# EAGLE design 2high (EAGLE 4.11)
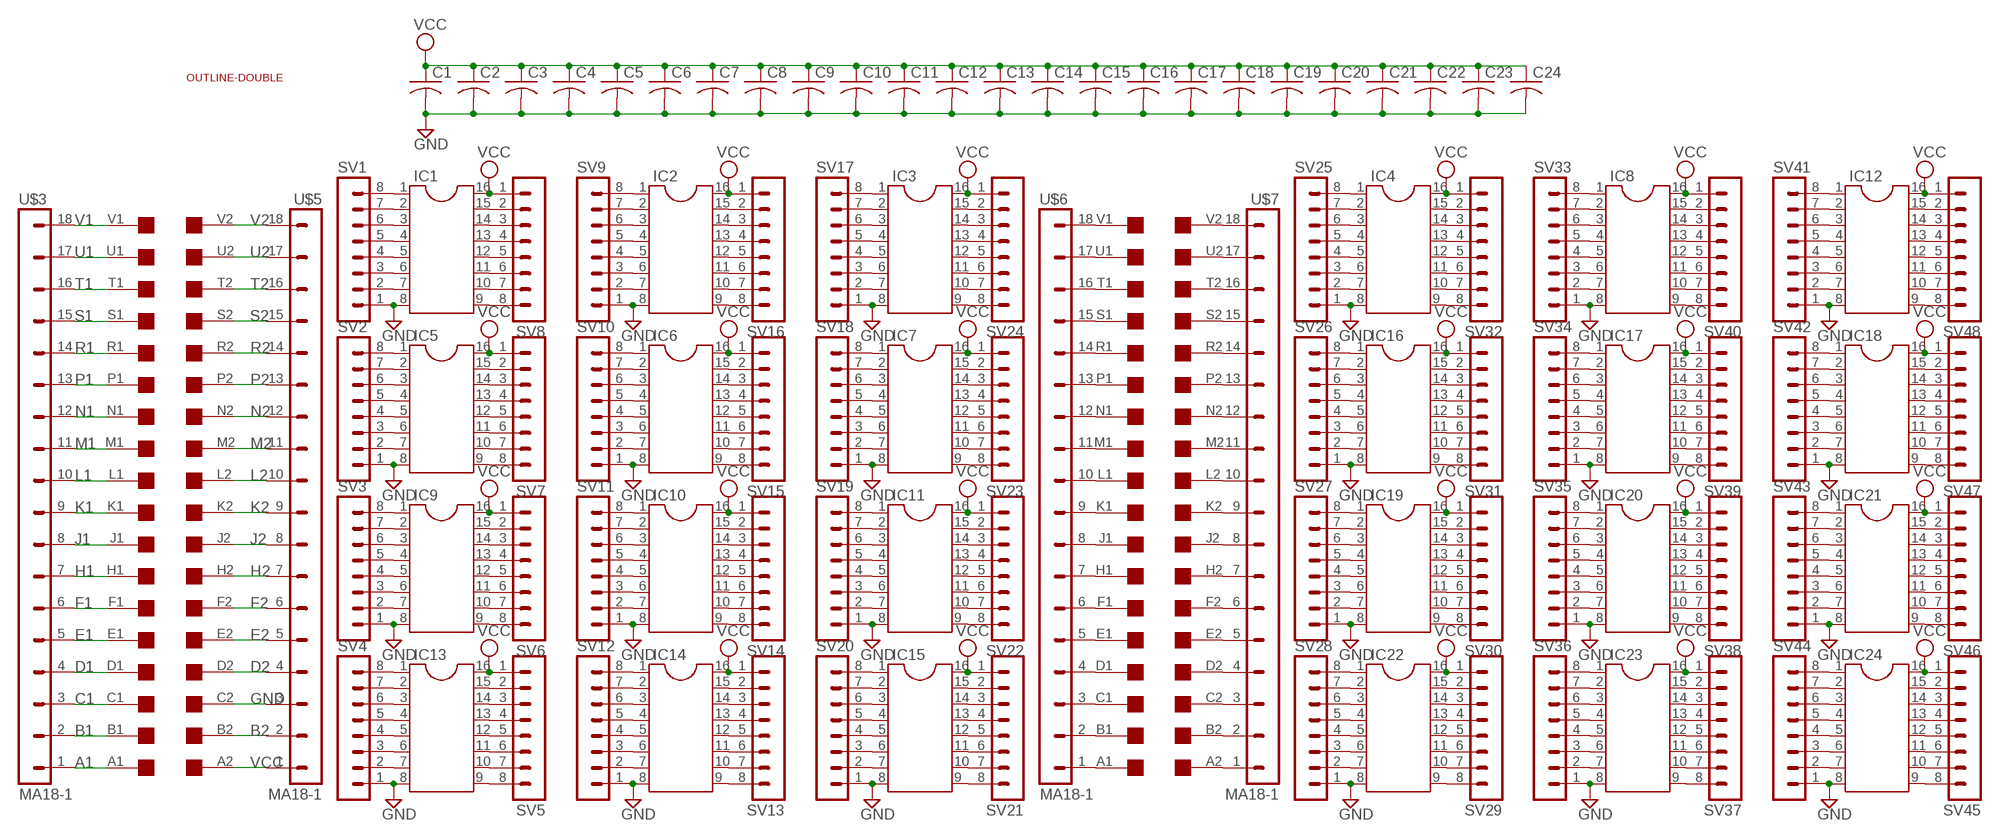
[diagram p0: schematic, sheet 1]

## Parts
C1  C-US050-025X075  [C050-025X075]
C2  C-US050-025X075  [C050-025X075]
C3  C-US050-025X075  [C050-025X075]
C4  C-US050-025X075  [C050-025X075]
C5  C-US050-025X075  [C050-025X075]
C6  C-US050-025X075  [C050-025X075]
C7  C-US050-025X075  [C050-025X075]
C8  C-US050-025X075  [C050-025X075]
C9  C-US050-025X075  [C050-025X075]
C10  C-US050-025X075  [C050-025X075]
C11  C-US050-025X075  [C050-025X075]
C12  C-US050-025X075  [C050-025X075]
C13  C-US050-025X075  [C050-025X075]
C14  C-US050-025X075  [C050-025X075]
C15  C-US050-025X075  [C050-025X075]
C16  C-US050-025X075  [C050-025X075]
C17  C-US050-025X075  [C050-025X075]
C18  C-US050-025X075  [C050-025X075]
C19  C-US050-025X075  [C050-025X075]
C20  C-US050-025X075  [C050-025X075]
C21  C-US050-025X075  [C050-025X075]
C22  C-US050-025X075  [C050-025X075]
C23  C-US050-025X075  [C050-025X075]
C24  C-US050-025X075  [C050-025X075]
IC1  DIL16  [DIL16]
IC2  DIL16  [DIL16]
IC3  DIL16  [DIL16]
IC4  DIL16  [DIL16]
IC5  DIL16  [DIL16]
IC6  DIL16  [DIL16]
IC7  DIL16  [DIL16]
IC8  DIL16  [DIL16]
IC9  DIL16  [DIL16]
IC10  DIL16  [DIL16]
IC11  DIL16  [DIL16]
IC12  DIL16  [DIL16]
IC13  DIL16  [DIL16]
IC14  DIL16  [DIL16]
IC15  DIL16  [DIL16]
IC16  DIL16  [DIL16]
IC17  DIL16  [DIL16]
IC18  DIL16  [DIL16]
IC19  DIL16  [DIL16]
IC20  DIL16  [DIL16]
IC21  DIL16  [DIL16]
IC22  DIL16  [DIL16]
IC23  DIL16  [DIL16]
IC24  DIL16  [DIL16]
SV1  MA08-1  [MA08-1]
SV2  MA08-1  [MA08-1]
SV3  MA08-1  [MA08-1]
SV4  MA08-1  [MA08-1]
SV5  MA08-1  [MA08-1]
SV6  MA08-1  [MA08-1]
SV7  MA08-1  [MA08-1]
SV8  MA08-1  [MA08-1]
SV9  MA08-1  [MA08-1]
SV10  MA08-1  [MA08-1]
SV11  MA08-1  [MA08-1]
SV12  MA08-1  [MA08-1]
SV13  MA08-1  [MA08-1]
SV14  MA08-1  [MA08-1]
SV15  MA08-1  [MA08-1]
SV16  MA08-1  [MA08-1]
SV17  MA08-1  [MA08-1]
SV18  MA08-1  [MA08-1]
SV19  MA08-1  [MA08-1]
SV20  MA08-1  [MA08-1]
SV21  MA08-1  [MA08-1]
SV22  MA08-1  [MA08-1]
SV23  MA08-1  [MA08-1]
SV24  MA08-1  [MA08-1]
SV25  MA08-1  [MA08-1]
SV26  MA08-1  [MA08-1]
SV27  MA08-1  [MA08-1]
SV28  MA08-1  [MA08-1]
SV29  MA08-1  [MA08-1]
SV30  MA08-1  [MA08-1]
SV31  MA08-1  [MA08-1]
SV32  MA08-1  [MA08-1]
SV33  MA08-1  [MA08-1]
SV34  MA08-1  [MA08-1]
SV35  MA08-1  [MA08-1]
SV36  MA08-1  [MA08-1]
SV37  MA08-1  [MA08-1]
SV38  MA08-1  [MA08-1]
SV39  MA08-1  [MA08-1]
SV40  MA08-1  [MA08-1]
SV41  MA08-1  [MA08-1]
SV42  MA08-1  [MA08-1]
SV43  MA08-1  [MA08-1]
SV44  MA08-1  [MA08-1]
SV45  MA08-1  [MA08-1]
SV46  MA08-1  [MA08-1]
SV47  MA08-1  [MA08-1]
SV48  MA08-1  [MA08-1]
U$1  OUTLINE-DOUBLE  [DOUBLE]
U$2  EDGE-2CONNECTOR  [EDGE-CON2]
U$3  MA18-1  [MA18-1]
U$4  EDGE-2CONNECTOR  [EDGE-CON2]
U$5  MA18-1  [MA18-1]
U$6  MA18-1  [MA18-1]
U$7  MA18-1  [MA18-1]

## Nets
A1: U$3.1 U$4.A1
B1: U$3.2 U$4.B1
B2: U$4.B2 U$5.2
C1: U$3.3 U$4.C1
D1: U$3.4 U$4.D1
D2: U$4.D2 U$5.4
E1: U$3.5 U$4.E1
E2: U$4.E2 U$5.5
F1: U$3.6 U$4.F1
F2: U$4.F2 U$5.6
GND: C1.2 C2.2 C3.2 C4.2 C5.2 C6.2 C7.2 C8.2 C9.2 C10.2 C11.2 C12.2 C13.2 C14.2 C15.2 C16.2 C17.2 C18.2 C19.2 C20.2 C21.2 C22.2 C23.2 C24.2 IC1.8 IC2.8 IC3.8 IC4.8 IC5.8 IC6.8 IC7.8 IC8.8 IC9.8 IC10.8 IC11.8 IC12.8 IC13.8 IC14.8 IC15.8 IC16.8 IC17.8 IC18.8 IC19.8 IC20.8 IC21.8 IC22.8 IC23.8 IC24.8 SV1.1 SV2.1 SV3.1 SV4.1 SV9.1 SV10.1 SV11.1 SV12.1 SV17.1 SV18.1 SV19.1 SV20.1 SV25.1 SV26.1 SV27.1 SV28.1 SV33.1 SV34.1 SV35.1 SV36.1 SV41.1 SV42.1 SV43.1 SV44.1 U$4.C2 U$5.3
H1: U$3.7 U$4.H1
H2: U$4.H2 U$5.7
J1: U$3.8 U$4.J1
J2: U$4.J2 U$5.8
K1: U$3.9 U$4.K1
K2: U$4.K2 U$5.9
L1: U$3.10 U$4.L1
L2: U$4.L2 U$5.10
M1: U$3.11 U$4.M1
M2: U$4.M2 U$5.11
N1: U$3.12 U$4.N1
N2: U$4.N2 U$5.12
N$1: IC1.7 SV1.2
N$2: IC1.6 SV1.3
N$3: IC1.5 SV1.4
N$4: IC1.4 SV1.5
N$5: IC1.3 SV1.6
N$6: IC1.2 SV1.7
N$7: IC1.1 SV1.8
N$8: IC5.7 SV2.2
N$9: IC5.6 SV2.3
N$10: IC5.5 SV2.4
N$11: IC5.4 SV2.5
N$12: IC5.3 SV2.6
N$13: IC5.2 SV2.7
N$14: IC5.1 SV2.8
N$15: IC9.7 SV3.2
N$16: IC9.6 SV3.3
N$17: IC9.5 SV3.4
N$18: IC9.4 SV3.5
N$19: IC9.3 SV3.6
N$20: IC9.2 SV3.7
N$21: IC9.1 SV3.8
N$22: IC13.7 SV4.2
N$23: IC13.6 SV4.3
N$24: IC13.5 SV4.4
N$25: IC13.4 SV4.5
N$26: IC13.3 SV4.6
N$27: IC13.2 SV4.7
N$28: IC13.1 SV4.8
N$29: IC2.1 SV9.8
N$30: IC2.2 SV9.7
N$31: IC2.3 SV9.6
N$32: IC2.4 SV9.5
N$33: IC2.5 SV9.4
N$34: IC2.6 SV9.3
N$35: IC2.7 SV9.2
N$36: IC6.1 SV10.8
N$37: IC6.2 SV10.7
N$38: IC6.3 SV10.6
N$39: IC6.4 SV10.5
N$40: IC6.5 SV10.4
N$41: IC6.6 SV10.3
N$42: IC6.7 SV10.2
N$43: IC10.1 SV11.8
N$44: IC10.2 SV11.7
N$45: IC10.3 SV11.6
N$46: IC10.4 SV11.5
N$47: IC10.5 SV11.4
N$48: IC10.6 SV11.3
N$49: IC10.7 SV11.2
N$50: IC14.1 SV12.8
N$51: IC14.2 SV12.7
N$52: IC14.3 SV12.6
N$53: IC14.4 SV12.5
N$54: IC14.5 SV12.4
N$55: IC14.6 SV12.3
N$56: IC14.7 SV12.2
N$57: IC6.15 SV15.2
N$58: IC6.14 SV15.3
N$59: IC6.13 SV15.4
N$60: IC6.12 SV15.5
N$61: IC6.11 SV15.6
N$62: IC6.10 SV15.7
N$63: IC6.9 SV15.8
N$64: IC10.15 SV14.2
N$65: IC10.14 SV14.3
N$66: IC10.13 SV14.4
N$67: IC10.12 SV14.5
N$68: IC10.11 SV14.6
N$69: IC10.10 SV14.7
N$70: IC10.9 SV14.8
N$71: IC1.9 SV8.8
N$72: IC1.10 SV8.7
N$73: IC1.11 SV8.6
N$74: IC1.12 SV8.5
N$75: IC1.13 SV8.4
N$76: IC1.14 SV8.3
N$77: IC1.15 SV8.2
N$78: IC5.9 SV7.8
N$79: IC5.10 SV7.7
N$80: IC5.11 SV7.6
N$81: IC5.12 SV7.5
N$82: IC5.13 SV7.4
N$83: IC5.14 SV7.3
N$84: IC5.15 SV7.2
N$85: IC2.15 SV16.2
N$86: IC2.14 SV16.3
N$87: IC2.13 SV16.4
N$88: IC2.12 SV16.5
N$89: IC2.11 SV16.6
N$90: IC2.10 SV16.7
N$91: IC2.9 SV16.8
N$92: IC13.15 SV5.2
N$93: IC13.14 SV5.3
N$94: IC13.13 SV5.4
N$95: IC13.12 SV5.5
N$96: IC13.11 SV5.6
N$97: IC13.10 SV5.7
N$98: IC13.9 SV5.8
N$99: IC9.15 SV6.2
N$100: IC9.14 SV6.3
N$101: IC9.13 SV6.4
N$102: IC9.12 SV6.5
N$103: IC9.11 SV6.6
N$104: IC9.10 SV6.7
N$105: IC9.9 SV6.8
N$106: IC14.15 SV13.2
N$107: IC14.14 SV13.3
N$108: IC14.13 SV13.4
N$109: IC14.12 SV13.5
N$110: IC14.11 SV13.6
N$111: IC14.10 SV13.7
N$112: IC14.9 SV13.8
N$113: IC3.7 SV17.2
N$114: IC3.6 SV17.3
N$115: IC3.5 SV17.4
N$116: IC3.4 SV17.5
N$117: IC3.3 SV17.6
N$118: IC3.2 SV17.7
N$119: IC3.1 SV17.8
N$120: IC7.7 SV18.2
N$121: IC7.6 SV18.3
N$122: IC7.5 SV18.4
N$123: IC7.4 SV18.5
N$124: IC7.3 SV18.6
N$125: IC7.2 SV18.7
N$126: IC7.1 SV18.8
N$127: IC11.7 SV19.2
N$128: IC11.6 SV19.3
N$129: IC11.5 SV19.4
N$130: IC11.4 SV19.5
N$131: IC11.3 SV19.6
N$132: IC11.2 SV19.7
N$133: IC11.1 SV19.8
N$134: IC15.7 SV20.2
N$135: IC15.6 SV20.3
N$136: IC15.5 SV20.4
N$137: IC15.4 SV20.5
N$138: IC15.3 SV20.6
N$139: IC15.2 SV20.7
N$140: IC15.1 SV20.8
N$141: IC15.15 SV21.2
N$142: IC15.14 SV21.3
N$143: IC15.13 SV21.4
N$144: IC15.12 SV21.5
N$145: IC15.11 SV21.6
N$146: IC15.10 SV21.7
N$147: IC15.9 SV21.8
N$148: IC11.15 SV22.2
N$149: IC11.14 SV22.3
N$150: IC11.13 SV22.4
N$151: IC11.12 SV22.5
N$152: IC11.11 SV22.6
N$153: IC11.10 SV22.7
N$154: IC11.9 SV22.8
N$155: IC7.15 SV23.2
N$156: IC7.14 SV23.3
N$157: IC7.13 SV23.4
N$158: IC7.12 SV23.5
N$159: IC7.11 SV23.6
N$160: IC7.10 SV23.7
N$161: IC7.9 SV23.8
N$162: IC3.15 SV24.2
N$163: IC3.14 SV24.3
N$164: IC3.13 SV24.4
N$165: IC3.12 SV24.5
N$166: IC3.11 SV24.6
N$167: IC3.10 SV24.7
N$168: IC3.9 SV24.8
N$169: U$2.A2 U$7.1
N$170: U$2.A1 U$6.1
N$171: U$2.B1 U$6.2
N$172: U$2.B2 U$7.2
N$173: U$2.C2 U$7.3
N$174: U$2.C1 U$6.3
N$175: U$2.D1 U$6.4
N$176: U$2.D2 U$7.4
N$177: U$2.E2 U$7.5
N$178: U$2.E1 U$6.5
N$179: U$2.F1 U$6.6
N$180: U$2.F2 U$7.6
N$181: U$2.H2 U$7.7
N$182: U$2.H1 U$6.7
N$183: U$2.J1 U$6.8
N$184: U$2.J2 U$7.8
N$185: U$2.K2 U$7.9
N$186: U$2.K1 U$6.9
N$187: U$2.L1 U$6.10
N$188: U$2.L2 U$7.10
N$189: U$2.M2 U$7.11
N$190: U$2.M1 U$6.11
N$191: U$2.N1 U$6.12
N$192: U$2.P1 U$6.13
N$193: U$2.P2 U$7.13
N$194: U$2.N2 U$7.12
N$195: U$2.V1 U$6.18
N$196: U$2.U1 U$6.17
N$197: U$2.T1 U$6.16
N$198: U$2.S1 U$6.15
N$199: U$2.R1 U$6.14
N$200: U$2.V2 U$7.18
N$201: U$2.U2 U$7.17
N$202: U$2.T2 U$7.16
N$203: U$2.S2 U$7.15
N$204: U$2.R2 U$7.14
N$205: IC4.7 SV25.2
N$206: IC4.6 SV25.3
N$207: IC4.5 SV25.4
N$208: IC4.4 SV25.5
N$209: IC4.3 SV25.6
N$210: IC4.2 SV25.7
N$211: IC4.1 SV25.8
N$212: IC16.7 SV26.2
N$213: IC16.6 SV26.3
N$214: IC16.5 SV26.4
N$215: IC16.4 SV26.5
N$216: IC16.3 SV26.6
N$217: IC16.2 SV26.7
N$218: IC16.1 SV26.8
N$219: IC19.7 SV27.2
N$220: IC19.6 SV27.3
N$221: IC19.5 SV27.4
N$222: IC19.4 SV27.5
N$223: IC19.3 SV27.6
N$224: IC19.2 SV27.7
N$225: IC19.1 SV27.8
N$226: IC22.7 SV28.2
N$227: IC22.6 SV28.3
N$228: IC22.5 SV28.4
N$229: IC22.4 SV28.5
N$230: IC22.3 SV28.6
N$231: IC22.2 SV28.7
N$232: IC22.1 SV28.8
N$233: IC8.1 SV33.8
N$234: IC8.2 SV33.7
N$235: IC8.3 SV33.6
N$236: IC8.4 SV33.5
N$237: IC8.5 SV33.4
N$238: IC8.6 SV33.3
N$239: IC8.7 SV33.2
N$240: IC17.1 SV34.8
N$241: IC17.2 SV34.7
N$242: IC17.3 SV34.6
N$243: IC17.4 SV34.5
N$244: IC17.5 SV34.4
N$245: IC17.6 SV34.3
N$246: IC17.7 SV34.2
N$247: IC20.1 SV35.8
N$248: IC20.2 SV35.7
N$249: IC20.3 SV35.6
N$250: IC20.4 SV35.5
N$251: IC20.5 SV35.4
N$252: IC20.6 SV35.3
N$253: IC20.7 SV35.2
N$254: IC23.1 SV36.8
N$255: IC23.2 SV36.7
N$256: IC23.3 SV36.6
N$257: IC23.4 SV36.5
N$258: IC23.5 SV36.4
N$259: IC23.6 SV36.3
N$260: IC23.7 SV36.2
N$261: IC17.15 SV39.2
N$262: IC17.14 SV39.3
N$263: IC17.13 SV39.4
N$264: IC17.12 SV39.5
N$265: IC17.11 SV39.6
N$266: IC17.10 SV39.7
N$267: IC17.9 SV39.8
N$268: IC20.15 SV38.2
N$269: IC20.14 SV38.3
N$270: IC20.13 SV38.4
N$271: IC20.12 SV38.5
N$272: IC20.11 SV38.6
N$273: IC20.10 SV38.7
N$274: IC20.9 SV38.8
N$275: IC4.9 SV32.8
N$276: IC4.10 SV32.7
N$277: IC4.11 SV32.6
N$278: IC4.12 SV32.5
N$279: IC4.13 SV32.4
N$280: IC4.14 SV32.3
N$281: IC4.15 SV32.2
N$282: IC16.9 SV31.8
N$283: IC16.10 SV31.7
N$284: IC16.11 SV31.6
N$285: IC16.12 SV31.5
N$286: IC16.13 SV31.4
N$287: IC16.14 SV31.3
N$288: IC16.15 SV31.2
N$289: IC8.15 SV40.2
N$290: IC8.14 SV40.3
N$291: IC8.13 SV40.4
N$292: IC8.12 SV40.5
N$293: IC8.11 SV40.6
N$294: IC8.10 SV40.7
N$295: IC8.9 SV40.8
N$296: IC22.15 SV29.2
N$297: IC22.14 SV29.3
N$298: IC22.13 SV29.4
N$299: IC22.12 SV29.5
N$300: IC22.11 SV29.6
N$301: IC22.10 SV29.7
N$302: IC22.9 SV29.8
N$303: IC19.15 SV30.2
N$304: IC19.14 SV30.3
N$305: IC19.13 SV30.4
N$306: IC19.12 SV30.5
N$307: IC19.11 SV30.6
N$308: IC19.10 SV30.7
N$309: IC19.9 SV30.8
N$310: IC23.15 SV37.2
N$311: IC23.14 SV37.3
N$312: IC23.13 SV37.4
N$313: IC23.12 SV37.5
N$314: IC23.11 SV37.6
N$315: IC23.10 SV37.7
N$316: IC23.9 SV37.8
N$317: IC12.7 SV41.2
N$318: IC12.6 SV41.3
N$319: IC12.5 SV41.4
N$320: IC12.4 SV41.5
N$321: IC12.3 SV41.6
N$322: IC12.2 SV41.7
N$323: IC12.1 SV41.8
N$324: IC18.7 SV42.2
N$325: IC18.6 SV42.3
N$326: IC18.5 SV42.4
N$327: IC18.4 SV42.5
N$328: IC18.3 SV42.6
N$329: IC18.2 SV42.7
N$330: IC18.1 SV42.8
N$331: IC21.7 SV43.2
N$332: IC21.6 SV43.3
N$333: IC21.5 SV43.4
N$334: IC21.4 SV43.5
N$335: IC21.3 SV43.6
N$336: IC21.2 SV43.7
N$337: IC21.1 SV43.8
N$338: IC24.7 SV44.2
N$339: IC24.6 SV44.3
N$340: IC24.5 SV44.4
N$341: IC24.4 SV44.5
N$342: IC24.3 SV44.6
N$343: IC24.2 SV44.7
N$344: IC24.1 SV44.8
N$345: IC24.15 SV45.2
N$346: IC24.14 SV45.3
N$347: IC24.13 SV45.4
N$348: IC24.12 SV45.5
N$349: IC24.11 SV45.6
N$350: IC24.10 SV45.7
N$351: IC24.9 SV45.8
N$352: IC21.15 SV46.2
N$353: IC21.14 SV46.3
N$354: IC21.13 SV46.4
N$355: IC21.12 SV46.5
N$356: IC21.11 SV46.6
N$357: IC21.10 SV46.7
N$358: IC21.9 SV46.8
N$359: IC18.15 SV47.2
N$360: IC18.14 SV47.3
N$361: IC18.13 SV47.4
N$362: IC18.12 SV47.5
N$363: IC18.11 SV47.6
N$364: IC18.10 SV47.7
N$365: IC18.9 SV47.8
N$366: IC12.15 SV48.2
N$367: IC12.14 SV48.3
N$368: IC12.13 SV48.4
N$369: IC12.12 SV48.5
N$370: IC12.11 SV48.6
N$371: IC12.10 SV48.7
N$372: IC12.9 SV48.8
P1: U$3.13 U$4.P1
P2: U$4.P2 U$5.13
R1: U$3.14 U$4.R1
R2: U$4.R2 U$5.14
S1: U$3.15 U$4.S1
S2: U$4.S2 U$5.15
T1: U$3.16 U$4.T1
T2: U$4.T2 U$5.16
U1: U$3.17 U$4.U1
U2: U$4.U2 U$5.17
V1: U$3.18 U$4.V1
V2: U$4.V2 U$5.18
VCC: C1.1 C2.1 C3.1 C4.1 C5.1 C6.1 C7.1 C8.1 C9.1 C10.1 C11.1 C12.1 C13.1 C14.1 C15.1 C16.1 C17.1 C18.1 C19.1 C20.1 C21.1 C22.1 C23.1 C24.1 IC1.16 IC2.16 IC3.16 IC4.16 IC5.16 IC6.16 IC7.16 IC8.16 IC9.16 IC10.16 IC11.16 IC12.16 IC13.16 IC14.16 IC15.16 IC16.16 IC17.16 IC18.16 IC19.16 IC20.16 IC21.16 IC22.16 IC23.16 IC24.16 SV5.1 SV6.1 SV7.1 SV8.1 SV13.1 SV14.1 SV15.1 SV16.1 SV21.1 SV22.1 SV23.1 SV24.1 SV29.1 SV30.1 SV31.1 SV32.1 SV37.1 SV38.1 SV39.1 SV40.1 SV45.1 SV46.1 SV47.1 SV48.1 U$4.A2 U$5.1

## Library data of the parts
C1-C24 = rcl:C-US: CAPACITOR, American symbol
IC1-IC24 = ic-package:DIL16: Dual In Line
SV1-SV48 = con-lstb:MA08-1: PIN HEADER
U$1 = dec-con:OUTLINE-*: Board outlines for DEC boards.
U$2 U$4 = dec-con:EDGE-2: Double-Sided DEC edge connector.
U$3 U$5-U$7 = dec-con:MA18-1

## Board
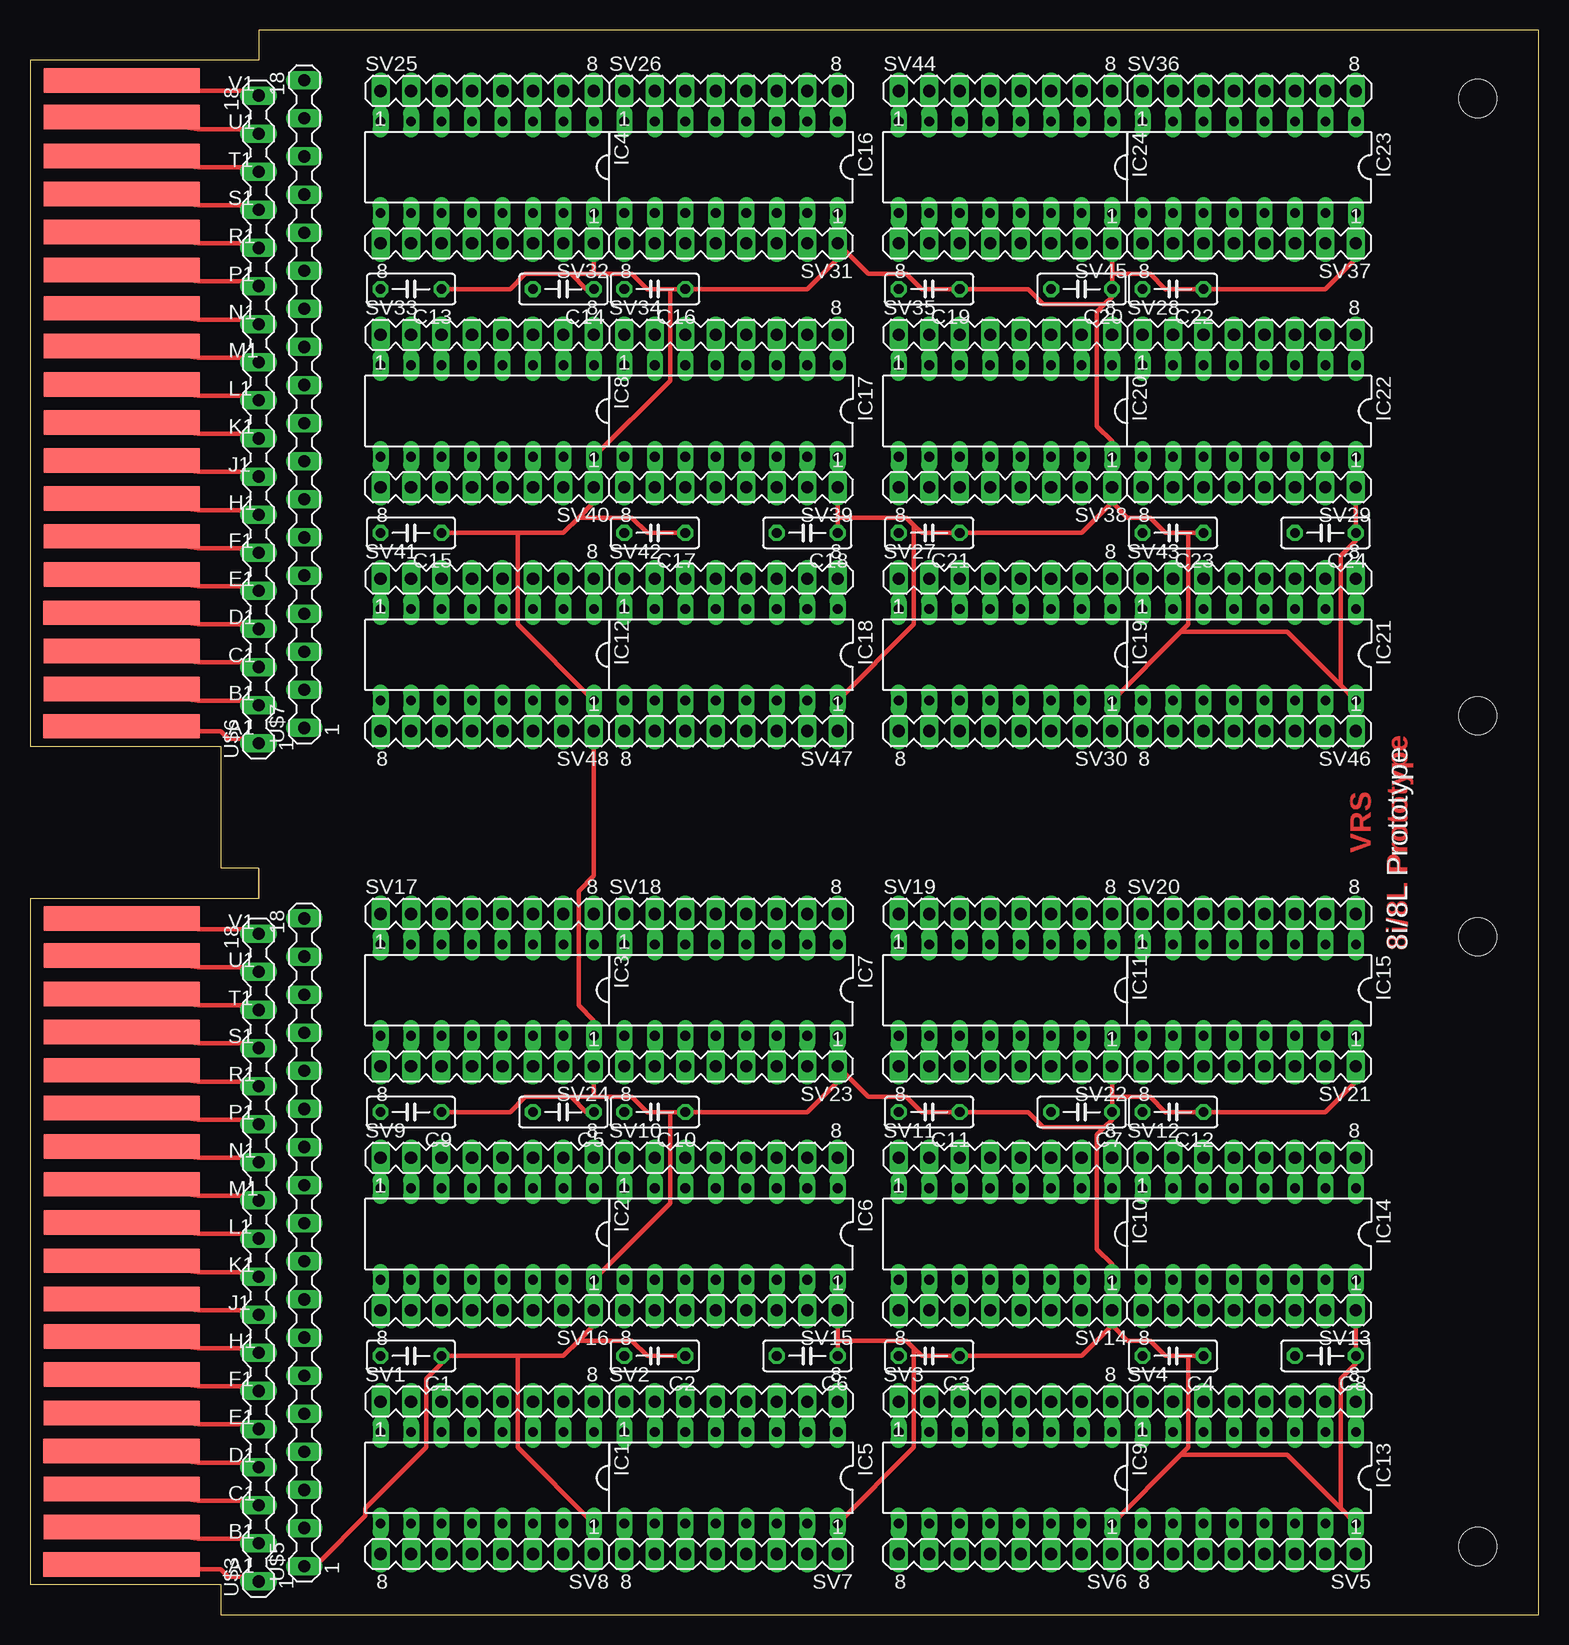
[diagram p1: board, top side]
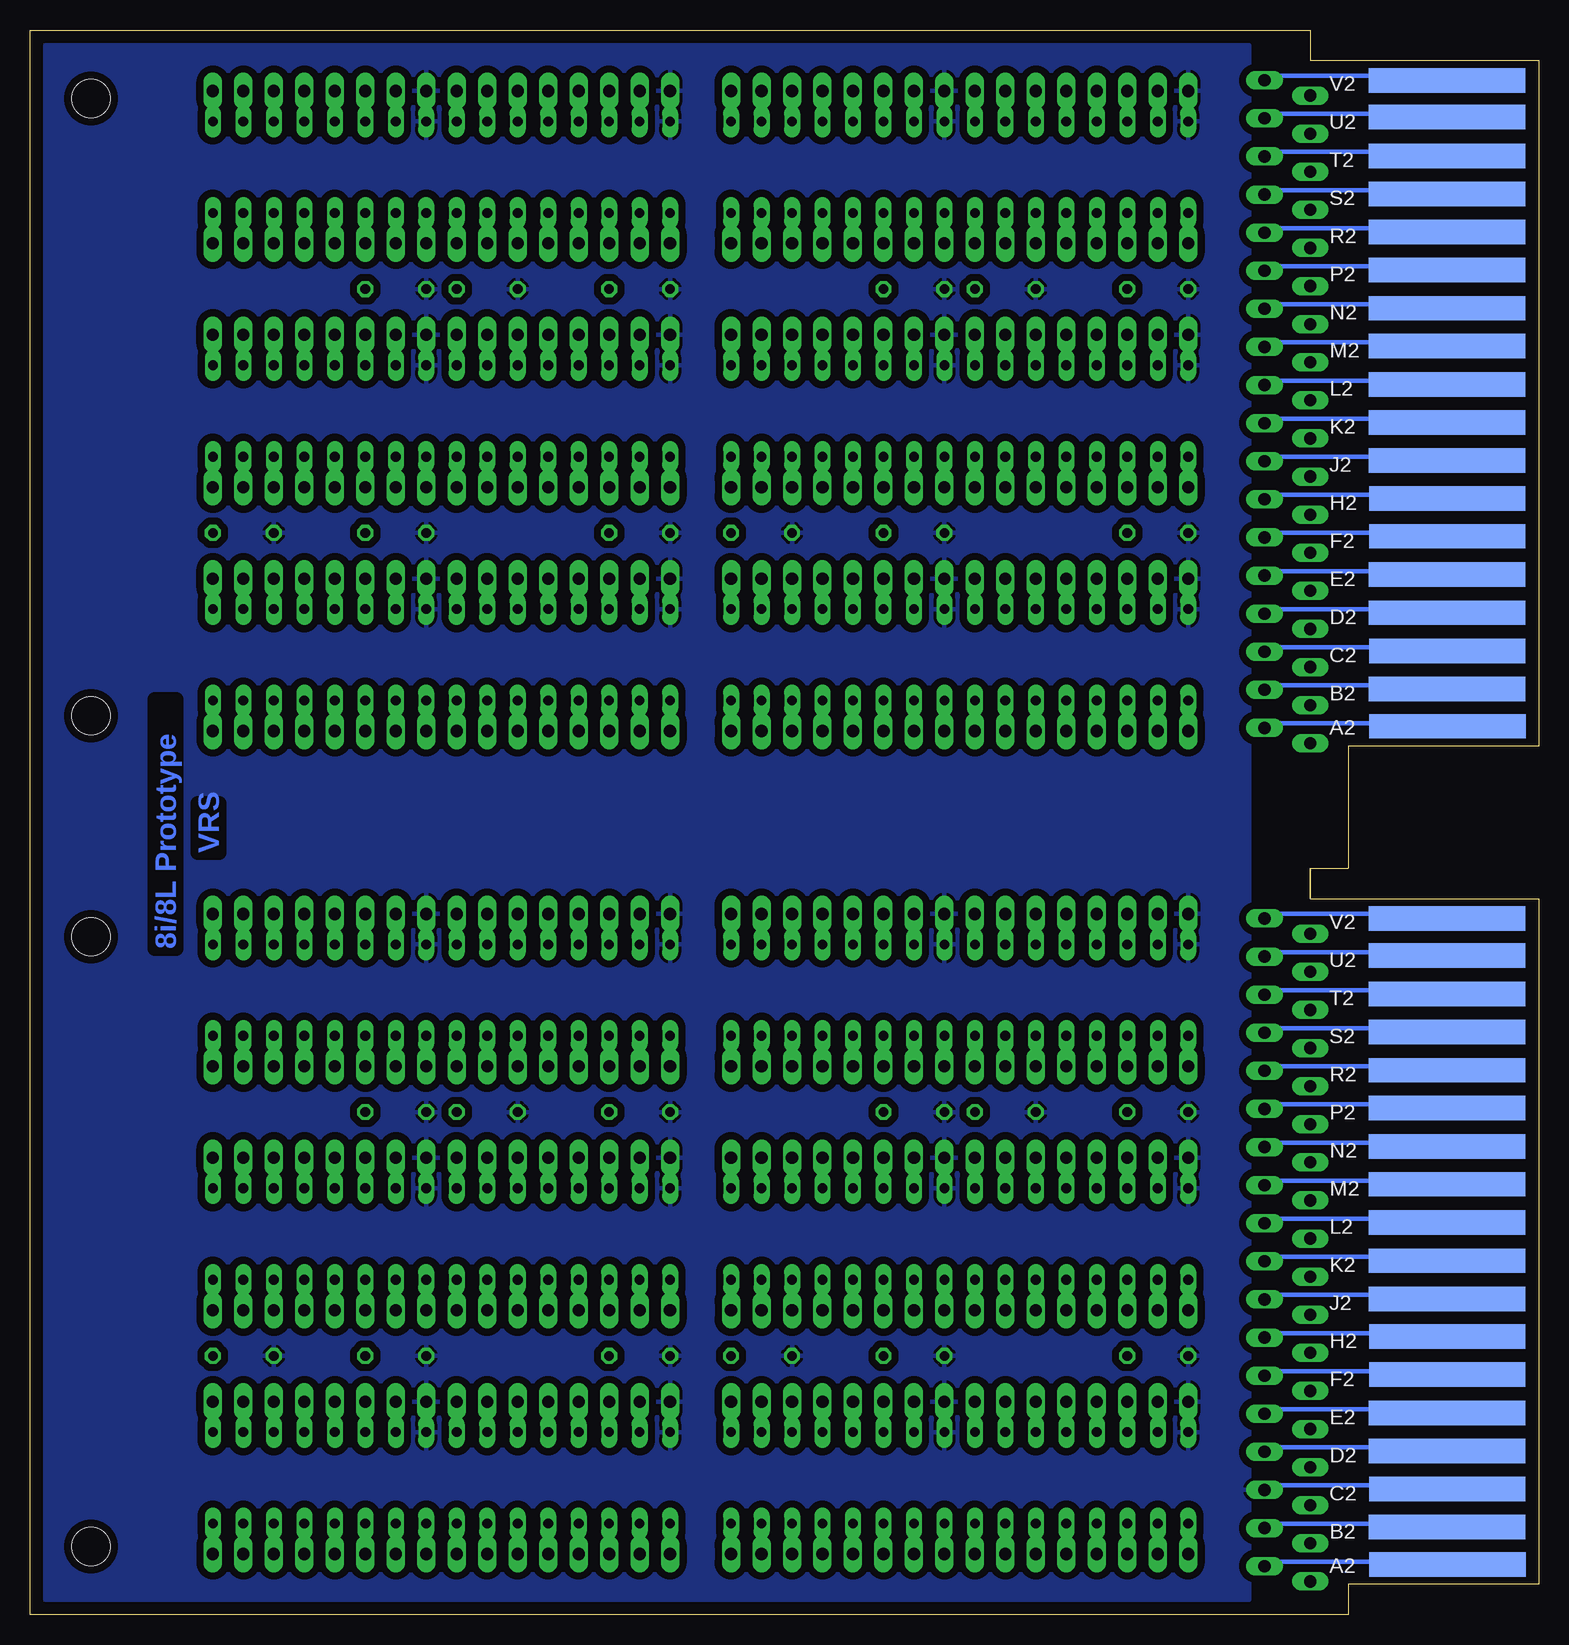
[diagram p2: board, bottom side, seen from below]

Size 125.73 x 132.08 mm. Coordinates in mm from the lower left corner, seen from the top.
Copper layers (1*16): Top 0.035mm / dielectric 1.5mm / Bottom 0.035mm
Design rules "olimex10mil": minimum track width 15mil, minimum drill 24mil, track to track 15mil, track to pad 10mil, pad to pad 10mil, via to via 10mil, smd to smd 10mil, copper to edge 25mil, drill to drill 10mil, minimum pad ring 10mil, minimum via ring 8mil, stop-mask expansion 0mil, vias tented up to drill 0mil, thermal gap 10mil

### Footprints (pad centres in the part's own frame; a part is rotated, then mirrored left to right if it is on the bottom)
C050-025X075 = drill 0.813 octagon: 1 -2.54,0; 2 2.54,0
DIL16 = drill 0.813 long: 1 -8.89,-3.81; 2 -6.35,-3.81; 3 -3.81,-3.81; 4 -1.27,-3.81; 5 1.27,-3.81; 6 3.81,-3.81; 7 6.35,-3.81; 8 8.89,-3.81; 9 8.89,3.81; 10 6.35,3.81; 11 3.81,3.81; 12 1.27,3.81; 13 -1.27,3.81; 14 -3.81,3.81; 15 -6.35,3.81; 16 -8.89,3.81
MA08-1 = drill 1.016 long: 1 -8.89,0; 2 -6.35,0; 3 -3.81,0; 4 -1.27,0; 5 1.27,0; 6 3.81,0; 7 6.35,0; 8 8.89,0
DOUBLE = hole 3.175: 120.65,56.515; 120.65,5.715; 120.65,74.93; 120.65,126.365
EDGE-CON2 = smd 13.017 x 2.032: A1 7.633,4.207; B1 7.639,7.327; C1 7.636,10.489; D1 7.633,13.665; E1 7.642,16.84; F1 7.642,20.041; H1 7.642,23.19; J1 7.642,26.34; K1 7.642,29.515; L1 7.642,32.69; M1 7.642,35.89; N1 7.642,39.04; P1 7.642,42.24; R1 7.642,45.39; S1 7.642,48.565; T1 7.642,51.74; U1 7.642,54.966; V1 7.642,58.026 | smd 13.017 x 2.032 bottom: A2 7.614,4.207; B2 7.642,7.328; C2 7.617,10.49; D2 7.642,13.665; E2 7.642,16.84; F2 7.617,20.041; H2 7.617,23.19; J2 7.642,26.34; K2 7.642,29.515; L2 7.642,32.69; M2 7.642,35.89; N2 7.642,39.04; P2 7.642,42.24; R2 7.642,45.39; S2 7.642,48.565; T2 7.642,51.74; U2 7.642,54.966; V2 7.642,58.026
MA18-1 = drill 1.016 long: 1 -25.146,0; 2 -21.971,0; 3 -18.796,0; 4 -15.621,0; 5 -12.446,0; 6 -9.271,0; 7 -6.096,0; 8 -2.921,0; 9 0.254,0; 10 3.429,0; 11 6.604,0; 12 9.779,0; 13 12.954,0; 14 16.129,0; 15 19.304,0; 16 22.479,0; 17 25.654,0; 18 28.829,0

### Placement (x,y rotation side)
C1  31.75,21.59 180 top
C2  52.07,21.59 180 top
C3  74.93,21.59 180 top
C4  95.25,21.59 180 top
C5  44.45,41.91 180 top
C6  64.77,21.59 180 top
C7  87.63,41.91 180 top
C8  107.95,21.59 180 top
C9  31.75,41.91 180 top
C10  52.07,41.91 180 top
C11  74.93,41.91 180 top
C12  95.25,41.91 180 top
C13  31.75,110.49 180 top
C14  44.45,110.49 180 top
C15  31.75,90.17 180 top
C16  52.07,110.49 180 top
C17  52.07,90.17 180 top
C18  64.77,90.17 180 top
C19  74.93,110.49 180 top
C20  87.63,110.49 180 top
C21  74.93,90.17 180 top
C22  95.25,110.49 180 top
C23  95.25,90.17 180 top
C24  107.95,90.17 180 top
IC1  38.1,11.43 180 top
IC2  38.1,31.75 180 top
IC3  38.1,52.07 180 top
IC4  38.1,120.65 180 top
IC5  58.42,11.43 180 top
IC6  58.42,31.75 180 top
IC7  58.42,52.07 180 top
IC8  38.1,100.33 180 top
IC9  81.28,11.43 180 top
IC10  81.28,31.75 180 top
IC11  81.28,52.07 180 top
IC12  38.1,80.01 180 top
IC13  101.6,11.43 180 top
IC14  101.6,31.75 180 top
IC15  101.6,52.07 180 top
IC16  58.42,120.65 180 top
IC17  58.42,100.33 180 top
IC18  58.42,80.01 180 top
IC19  81.28,80.01 180 top
IC20  81.28,100.33 180 top
IC21  101.6,80.01 180 top
IC22  101.6,100.33 180 top
IC23  101.6,120.65 180 top
IC24  81.28,120.65 180 top
SV1  38.1,17.78 0 top
SV2  58.42,17.78 0 top
SV3  81.28,17.78 0 top
SV4  101.6,17.78 0 top
SV5  101.6,5.08 180 top
SV6  81.28,5.08 180 top
SV7  58.42,5.08 180 top
SV8  38.1,5.08 180 top
SV9  38.1,38.1 0 top
SV10  58.42,38.1 0 top
SV11  81.28,38.1 0 top
SV12  101.6,38.1 0 top
SV13  101.6,25.4 180 top
SV14  81.28,25.4 180 top
SV15  58.42,25.4 180 top
SV16  38.1,25.4 180 top
SV17  38.1,58.42 0 top
SV18  58.42,58.42 0 top
SV19  81.28,58.42 0 top
SV20  101.6,58.42 0 top
SV21  101.6,45.72 180 top
SV22  81.28,45.72 180 top
SV23  58.42,45.72 180 top
SV24  38.1,45.72 180 top
SV25  38.1,127 0 top
SV26  58.42,127 0 top
SV27  81.28,86.36 0 top
SV28  101.6,106.68 0 top
SV29  101.6,93.98 180 top
SV30  81.28,73.66 180 top
SV31  58.42,114.3 180 top
SV32  38.1,114.3 180 top
SV33  38.1,106.68 0 top
SV34  58.42,106.68 0 top
SV35  81.28,106.68 0 top
SV36  101.6,127 0 top
SV37  101.6,114.3 180 top
SV38  81.28,93.98 180 top
SV39  58.42,93.98 180 top
SV40  38.1,93.98 180 top
SV41  38.1,86.36 0 top
SV42  58.42,86.36 0 top
SV43  101.6,86.36 0 top
SV44  81.28,127 0 top
SV45  81.28,114.3 180 top
SV46  101.6,73.66 180 top
SV47  58.42,73.66 180 top
SV48  38.1,73.66 180 top
U$1  0,0 0 top
U$2  0,69.85 0 top
U$3  19.05,27.94 90 top
U$4  0,0 0 top
U$5  22.86,29.21 90 top
U$6  19.05,97.79 90 top
U$7  22.86,99.06 90 top

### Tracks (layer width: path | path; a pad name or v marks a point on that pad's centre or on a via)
A1
  Top 0.381: U$3.1 17.78,3.17 16.51,3.17 15.88,3.81 13.97,3.81 U$4.A1
B1
  Top 0.381: U$3.2 17.78,6.35 13.97,6.35 U$4.B1
B2
  Bottom 0.381: U$5.2 21.59,7.62 13.97,7.62 U$4.B2
C1
  Top 0.381: U$3.3 17.78,9.53 13.97,9.53 U$4.C1
D1
  Top 0.381: U$3.4 17.78,12.7 13.97,12.7 U$4.D1
D2
  Bottom 0.381: U$5.4 21.59,13.97 13.97,13.97 U$4.D2
E1
  Top 0.381: U$3.5 17.78,15.88 13.97,15.88 U$4.E1
E2
  Bottom 0.381: U$5.5 21.59,17.14 13.97,17.14 U$4.E2
F1
  Top 0.381: U$3.6 17.78,19.05 13.97,19.05 U$4.F1
F2
  Bottom 0.381: U$5.6 21.59,20.32 13.97,20.32 U$4.F2
GND
  Bottom 0.381: 24.13,10.35 24.13,10.16 U$5.3 21.59,10.79 13.97,10.79 U$4.C2
  pour Bottom (isolate 0.61): 24.13,130.81 124.46,130.81 124.46,1.27 24.13,1.27
H1
  Top 0.381: U$3.7 17.78,22.23 13.97,22.23 U$4.H1
H2
  Bottom 0.381: U$5.7 21.59,23.5 13.97,23.5 U$4.H2
J1
  Top 0.381: U$3.8 17.78,25.4 13.97,25.4 U$4.J1
J2
  Bottom 0.381: U$5.8 21.59,26.67 13.97,26.67 U$4.J2
K1
  Top 0.381: U$3.9 17.78,28.57 13.97,28.57 U$4.K1
K2
  Bottom 0.381: U$5.9 21.59,29.84 13.97,29.84 U$4.K2
L1
  Top 0.381: U$3.10 17.78,31.75 13.97,31.75 U$4.L1
L2
  Bottom 0.381: U$5.10 21.59,33.02 13.97,33.02 U$4.L2
M1
  Top 0.381: U$3.11 17.78,34.92 13.97,34.92 U$4.M1
M2
  Bottom 0.381: U$5.11 21.59,36.2 13.97,36.2 U$4.M2
N1
  Top 0.381: U$3.12 17.78,38.1 13.97,38.1 U$4.N1
N2
  Bottom 0.381: U$5.12 21.59,39.37 13.97,39.37 U$4.N2
N$1
  Bottom 0.381: IC1.7 SV1.2
N$2
  Bottom 0.381: IC1.6 SV1.3
N$3
  Bottom 0.381: IC1.5 SV1.4
N$4
  Bottom 0.381: IC1.4 SV1.5
N$5
  Bottom 0.381: IC1.3 SV1.6
N$6
  Bottom 0.381: IC1.2 SV1.7
N$7
  Bottom 0.381: IC1.1 SV1.8
N$8
  Bottom 0.381: IC5.7 SV2.2
N$9
  Bottom 0.381: IC5.6 SV2.3
N$10
  Bottom 0.381: IC5.5 SV2.4
N$11
  Bottom 0.381: IC5.4 SV2.5
N$12
  Bottom 0.381: IC5.3 SV2.6
N$13
  Bottom 0.381: IC5.2 SV2.7
N$14
  Bottom 0.381: IC5.1 SV2.8
N$15
  Bottom 0.381: IC9.7 SV3.2
N$16
  Bottom 0.381: IC9.6 SV3.3
N$17
  Bottom 0.381: IC9.5 SV3.4
N$18
  Bottom 0.381: IC9.4 SV3.5
N$19
  Bottom 0.381: IC9.3 SV3.6
N$20
  Bottom 0.381: IC9.2 SV3.7
N$21
  Bottom 0.381: IC9.1 SV3.8
N$22
  Bottom 0.381: IC13.7 SV4.2
N$23
  Bottom 0.381: IC13.6 SV4.3
N$24
  Bottom 0.381: IC13.5 SV4.4
N$25
  Bottom 0.381: IC13.4 SV4.5
N$26
  Bottom 0.381: IC13.3 SV4.6
N$27
  Bottom 0.381: IC13.2 SV4.7
N$28
  Bottom 0.381: IC13.1 SV4.8
N$29
  Bottom 0.381: IC2.1 SV9.8
N$30
  Bottom 0.381: IC2.2 SV9.7
N$31
  Bottom 0.381: IC2.3 SV9.6
N$32
  Bottom 0.381: IC2.4 SV9.5
N$33
  Bottom 0.381: IC2.5 SV9.4
N$34
  Bottom 0.381: IC2.6 SV9.3
N$35
  Bottom 0.381: IC2.7 SV9.2
N$36
  Bottom 0.381: IC6.1 SV10.8
N$37
  Bottom 0.381: IC6.2 SV10.7
N$38
  Bottom 0.381: IC6.3 SV10.6
N$39
  Bottom 0.381: IC6.4 SV10.5
N$40
  Bottom 0.381: IC6.5 SV10.4
N$41
  Bottom 0.381: IC6.6 SV10.3
N$42
  Bottom 0.381: IC6.7 SV10.2
N$43
  Bottom 0.381: IC10.1 SV11.8
N$44
  Bottom 0.381: IC10.2 SV11.7
N$45
  Bottom 0.381: IC10.3 SV11.6
N$46
  Bottom 0.381: IC10.4 SV11.5
N$47
  Bottom 0.381: IC10.5 SV11.4
N$48
  Bottom 0.381: IC10.6 SV11.3
N$49
  Bottom 0.381: IC10.7 SV11.2
N$50
  Bottom 0.381: IC14.1 SV12.8
N$51
  Bottom 0.381: IC14.2 SV12.7
N$52
  Bottom 0.381: IC14.3 SV12.6
N$53
  Bottom 0.381: IC14.4 SV12.5
N$54
  Bottom 0.381: IC14.5 SV12.4
N$55
  Bottom 0.381: IC14.6 SV12.3
N$56
  Bottom 0.381: IC14.7 SV12.2
N$57
  Bottom 0.381: SV15.2 IC6.15
N$58
  Bottom 0.381: SV15.3 IC6.14
N$59
  Bottom 0.381: SV15.4 IC6.13
N$60
  Bottom 0.381: SV15.5 IC6.12
N$61
  Bottom 0.381: SV15.6 IC6.11
N$62
  Bottom 0.381: SV15.7 IC6.10
N$63
  Bottom 0.381: SV15.8 IC6.9
N$64
  Bottom 0.381: SV14.2 IC10.15
N$65
  Bottom 0.381: SV14.3 IC10.14
N$66
  Bottom 0.381: SV14.4 IC10.13
N$67
  Bottom 0.381: SV14.5 IC10.12
N$68
  Bottom 0.381: SV14.6 IC10.11
N$69
  Bottom 0.381: SV14.7 IC10.10
N$70
  Bottom 0.381: SV14.8 IC10.9
N$71
  Bottom 0.381: SV8.8 IC1.9
N$72
  Bottom 0.381: SV8.7 IC1.10
N$73
  Bottom 0.381: SV8.6 IC1.11
N$74
  Bottom 0.381: SV8.5 IC1.12
N$75
  Bottom 0.381: SV8.4 IC1.13
N$76
  Bottom 0.381: SV8.3 IC1.14
N$77
  Bottom 0.381: SV8.2 IC1.15
N$78
  Bottom 0.381: SV7.8 IC5.9
N$79
  Bottom 0.381: SV7.7 IC5.10
N$80
  Bottom 0.381: SV7.6 IC5.11
N$81
  Bottom 0.381: SV7.5 IC5.12
N$82
  Bottom 0.381: SV7.4 IC5.13
N$83
  Bottom 0.381: SV7.3 IC5.14
N$84
  Bottom 0.381: SV7.2 IC5.15
N$85
  Bottom 0.381: SV16.2 IC2.15
N$86
  Bottom 0.381: SV16.3 IC2.14
N$87
  Bottom 0.381: SV16.4 IC2.13
N$88
  Bottom 0.381: SV16.5 IC2.12
N$89
  Bottom 0.381: SV16.6 IC2.11
N$90
  Bottom 0.381: SV16.7 IC2.10
N$91
  Bottom 0.381: SV16.8 IC2.9
N$92
  Bottom 0.381: SV5.2 IC13.15
N$93
  Bottom 0.381: SV5.3 IC13.14
N$94
  Bottom 0.381: SV5.4 IC13.13
N$95
  Bottom 0.381: SV5.5 IC13.12
N$96
  Bottom 0.381: SV5.6 IC13.11
N$97
  Bottom 0.381: SV5.7 IC13.10
N$98
  Bottom 0.381: SV5.8 IC13.9
N$99
  Bottom 0.381: SV6.2 IC9.15
N$100
  Bottom 0.381: SV6.3 IC9.14
N$101
  Bottom 0.381: SV6.4 IC9.13
N$102
  Bottom 0.381: SV6.5 IC9.12
N$103
  Bottom 0.381: SV6.6 IC9.11
N$104
  Bottom 0.381: SV6.7 IC9.10
N$105
  Bottom 0.381: SV6.8 IC9.9
N$106
  Bottom 0.381: SV13.2 IC14.15
N$107
  Bottom 0.381: SV13.3 IC14.14
N$108
  Bottom 0.381: SV13.4 IC14.13
N$109
  Bottom 0.381: SV13.5 IC14.12
N$110
  Bottom 0.381: SV13.6 IC14.11
N$111
  Bottom 0.381: SV13.7 IC14.10
N$112
  Bottom 0.381: SV13.8 IC14.9
N$113
  Bottom 0.381: IC3.7 SV17.2
N$114
  Bottom 0.381: IC3.6 SV17.3
N$115
  Bottom 0.381: IC3.5 SV17.4
N$116
  Bottom 0.381: IC3.4 SV17.5
N$117
  Bottom 0.381: IC3.3 SV17.6
N$118
  Bottom 0.381: IC3.2 SV17.7
N$119
  Bottom 0.381: IC3.1 SV17.8
N$120
  Bottom 0.381: IC7.7 SV18.2
N$121
  Bottom 0.381: IC7.6 SV18.3
N$122
  Bottom 0.381: IC7.5 SV18.4
N$123
  Bottom 0.381: IC7.4 SV18.5
N$124
  Bottom 0.381: IC7.3 SV18.6
N$125
  Bottom 0.381: IC7.2 SV18.7
N$126
  Bottom 0.381: IC7.1 SV18.8
N$127
  Bottom 0.381: IC11.7 SV19.2
N$128
  Bottom 0.381: IC11.6 SV19.3
N$129
  Bottom 0.381: IC11.5 SV19.4
N$130
  Bottom 0.381: IC11.4 SV19.5
N$131
  Bottom 0.381: IC11.3 SV19.6
N$132
  Bottom 0.381: IC11.2 SV19.7
N$133
  Bottom 0.381: IC11.1 SV19.8
N$134
  Bottom 0.381: IC15.7 SV20.2
N$135
  Bottom 0.381: IC15.6 SV20.3
N$136
  Bottom 0.381: IC15.5 SV20.4
N$137
  Bottom 0.381: IC15.4 SV20.5
N$138
  Bottom 0.381: IC15.3 SV20.6
N$139
  Bottom 0.381: IC15.2 SV20.7
N$140
  Bottom 0.381: IC15.1 SV20.8
N$141
  Bottom 0.381: SV21.2 IC15.15
N$142
  Bottom 0.381: SV21.3 IC15.14
N$143
  Bottom 0.381: SV21.4 IC15.13
N$144
  Bottom 0.381: SV21.5 IC15.12
N$145
  Bottom 0.381: SV21.6 IC15.11
N$146
  Bottom 0.381: SV21.7 IC15.10
N$147
  Bottom 0.381: SV21.8 IC15.9
N$148
  Bottom 0.381: SV22.2 IC11.15
N$149
  Bottom 0.381: SV22.3 IC11.14
N$150
  Bottom 0.381: SV22.4 IC11.13
N$151
  Bottom 0.381: SV22.5 IC11.12
N$152
  Bottom 0.381: SV22.6 IC11.11
N$153
  Bottom 0.381: SV22.7 IC11.10
N$154
  Bottom 0.381: SV22.8 IC11.9
N$155
  Bottom 0.381: SV23.2 IC7.15
N$156
  Bottom 0.381: SV23.3 IC7.14
N$157
  Bottom 0.381: SV23.4 IC7.13
N$158
  Bottom 0.381: SV23.5 IC7.12
N$159
  Bottom 0.381: SV23.6 IC7.11
N$160
  Bottom 0.381: SV23.7 IC7.10
N$161
  Bottom 0.381: SV23.8 IC7.9
N$162
  Bottom 0.381: SV24.2 IC3.15
N$163
  Bottom 0.381: SV24.3 IC3.14
N$164
  Bottom 0.381: SV24.4 IC3.13
N$165
  Bottom 0.381: SV24.5 IC3.12
N$166
  Bottom 0.381: SV24.6 IC3.11
N$167
  Bottom 0.381: SV24.7 IC3.10
N$168
  Bottom 0.381: SV24.8 IC3.9
N$169
  Bottom 0.381: U$7.1 21.59,74.3 13.97,74.3 U$2.A2
N$170
  Top 0.381: U$6.1 17.78,73.03 16.51,73.03 15.88,73.66 13.97,73.66 U$2.A1
N$171
  Top 0.381: U$6.2 17.78,76.2 13.97,76.2 U$2.B1
N$172
  Bottom 0.381: U$7.2 21.59,77.47 13.97,77.47 U$2.B2
N$173
  Bottom 0.381: U$7.3 21.59,80.64 13.97,80.64 U$2.C2
N$174
  Top 0.381: U$6.3 17.78,79.38 13.97,79.38 U$2.C1
N$175
  Top 0.381: U$6.4 17.78,82.55 13.97,82.55 U$2.D1
N$176
  Bottom 0.381: U$7.4 21.59,83.82 13.97,83.82 U$2.D2
N$177
  Bottom 0.381: U$7.5 21.59,87 13.97,87 U$2.E2
N$178
  Top 0.381: U$6.5 17.78,85.72 13.97,85.72 U$2.E1
N$179
  Top 0.381: U$6.6 17.78,88.9 13.97,88.9 U$2.F1
N$180
  Bottom 0.381: U$7.6 21.59,90.17 13.97,90.17 U$2.F2
N$181
  Bottom 0.381: U$7.7 21.59,93.34 13.97,93.34 U$2.H2
N$182
  Top 0.381: U$6.7 17.78,92.08 13.97,92.08 U$2.H1
N$183
  Top 0.381: U$6.8 17.78,95.25 13.97,95.25 U$2.J1
N$184
  Bottom 0.381: U$7.8 21.59,96.52 13.97,96.52 U$2.J2
N$185
  Bottom 0.381: U$7.9 21.59,99.69 13.97,99.69 U$2.K2
N$186
  Top 0.381: U$6.9 17.78,98.42 13.97,98.42 U$2.K1
N$187
  Top 0.381: U$6.10 17.78,101.6 13.97,101.6 U$2.L1
N$188
  Bottom 0.381: U$7.10 21.59,102.87 13.97,102.87 U$2.L2
N$189
  Bottom 0.381: U$7.11 21.59,106.05 13.97,106.05 U$2.M2
N$190
  Top 0.381: U$6.11 17.78,104.78 13.97,104.78 U$2.M1
N$191
  Top 0.381: U$6.12 17.78,107.95 13.97,107.95 U$2.N1
N$192
  Top 0.381: U$6.13 17.78,111.12 13.97,111.12 U$2.P1
N$193
  Bottom 0.381: U$7.13 21.59,112.39 13.97,112.39 U$2.P2
N$194
  Bottom 0.381: U$7.12 21.59,109.22 13.97,109.22 U$2.N2
N$195
  Top 0.381: U$6.18 17.78,127 13.97,127 U$2.V1
N$196
  Top 0.381: U$6.17 17.78,123.83 13.97,123.83 U$2.U1
N$197
  Top 0.381: U$6.16 17.78,120.65 13.97,120.65 U$2.T1
N$198
  Top 0.381: U$6.15 17.78,117.47 13.97,117.47 U$2.S1
N$199
  Top 0.381: U$6.14 17.78,114.3 13.97,114.3 U$2.R1
N$200
  Bottom 0.381: U$7.18 21.59,128.27 13.97,128.27 U$2.V2
N$201
  Bottom 0.381: U$7.17 21.59,125.09 13.97,125.09 U$2.U2
N$202
  Bottom 0.381: U$7.16 21.59,121.92 13.97,121.92 U$2.T2
N$203
  Bottom 0.381: U$7.15 21.59,118.75 13.97,118.75 U$2.S2
N$204
  Bottom 0.381: U$7.14 21.59,115.57 13.97,115.57 U$2.R2
N$205
  Bottom 0.381: IC4.7 SV25.2
N$206
  Bottom 0.381: IC4.6 SV25.3
N$207
  Bottom 0.381: IC4.5 SV25.4
N$208
  Bottom 0.381: IC4.4 SV25.5
N$209
  Bottom 0.381: IC4.3 SV25.6
N$210
  Bottom 0.381: IC4.2 SV25.7
N$211
  Bottom 0.381: IC4.1 SV25.8
N$212
  Bottom 0.381: IC16.7 SV26.2
N$213
  Bottom 0.381: IC16.6 SV26.3
N$214
  Bottom 0.381: IC16.5 SV26.4
N$215
  Bottom 0.381: IC16.4 SV26.5
N$216
  Bottom 0.381: IC16.3 SV26.6
N$217
  Bottom 0.381: IC16.2 SV26.7
N$218
  Bottom 0.381: IC16.1 SV26.8
N$219
  Bottom 0.381: IC19.7 SV27.2
N$220
  Bottom 0.381: IC19.6 SV27.3
N$221
  Bottom 0.381: IC19.5 SV27.4
N$222
  Bottom 0.381: IC19.4 SV27.5
N$223
  Bottom 0.381: IC19.3 SV27.6
N$224
  Bottom 0.381: IC19.2 SV27.7
N$225
  Bottom 0.381: IC19.1 SV27.8
N$226
  Bottom 0.381: IC22.7 SV28.2
N$227
  Bottom 0.381: IC22.6 SV28.3
N$228
  Bottom 0.381: IC22.5 SV28.4
N$229
  Bottom 0.381: IC22.4 SV28.5
N$230
  Bottom 0.381: IC22.3 SV28.6
N$231
  Bottom 0.381: IC22.2 SV28.7
N$232
  Bottom 0.381: IC22.1 SV28.8
N$233
  Bottom 0.381: IC8.1 SV33.8
N$234
  Bottom 0.381: IC8.2 SV33.7
N$235
  Bottom 0.381: IC8.3 SV33.6
N$236
  Bottom 0.381: IC8.4 SV33.5
N$237
  Bottom 0.381: IC8.5 SV33.4
N$238
  Bottom 0.381: IC8.6 SV33.3
N$239
  Bottom 0.381: IC8.7 SV33.2
N$240
  Bottom 0.381: IC17.1 SV34.8
N$241
  Bottom 0.381: IC17.2 SV34.7
N$242
  Bottom 0.381: IC17.3 SV34.6
N$243
  Bottom 0.381: IC17.4 SV34.5
N$244
  Bottom 0.381: IC17.5 SV34.4
N$245
  Bottom 0.381: IC17.6 SV34.3
N$246
  Bottom 0.381: IC17.7 SV34.2
N$247
  Bottom 0.381: IC20.1 SV35.8
N$248
  Bottom 0.381: IC20.2 SV35.7
N$249
  Bottom 0.381: IC20.3 SV35.6
N$250
  Bottom 0.381: IC20.4 SV35.5
N$251
  Bottom 0.381: IC20.5 SV35.4
N$252
  Bottom 0.381: IC20.6 SV35.3
N$253
  Bottom 0.381: IC20.7 SV35.2
N$254
  Bottom 0.381: IC23.1 SV36.8
N$255
  Bottom 0.381: IC23.2 SV36.7
N$256
  Bottom 0.381: IC23.3 SV36.6
N$257
  Bottom 0.381: IC23.4 SV36.5
N$258
  Bottom 0.381: IC23.5 SV36.4
N$259
  Bottom 0.381: IC23.6 SV36.3
N$260
  Bottom 0.381: IC23.7 SV36.2
N$261
  Bottom 0.381: SV39.2 IC17.15
N$262
  Bottom 0.381: SV39.3 IC17.14
N$263
  Bottom 0.381: SV39.4 IC17.13
N$264
  Bottom 0.381: SV39.5 IC17.12
N$265
  Bottom 0.381: SV39.6 IC17.11
N$266
  Bottom 0.381: SV39.7 IC17.10
N$267
  Bottom 0.381: SV39.8 IC17.9
N$268
  Bottom 0.381: SV38.2 IC20.15
N$269
  Bottom 0.381: SV38.3 IC20.14
N$270
  Bottom 0.381: SV38.4 IC20.13
N$271
  Bottom 0.381: SV38.5 IC20.12
N$272
  Bottom 0.381: SV38.6 IC20.11
N$273
  Bottom 0.381: SV38.7 IC20.10
N$274
  Bottom 0.381: SV38.8 IC20.9
N$275
  Bottom 0.381: SV32.8 IC4.9
N$276
  Bottom 0.381: SV32.7 IC4.10
N$277
  Bottom 0.381: SV32.6 IC4.11
N$278
  Bottom 0.381: SV32.5 IC4.12
N$279
  Bottom 0.381: SV32.4 IC4.13
N$280
  Bottom 0.381: SV32.3 IC4.14
N$281
  Bottom 0.381: SV32.2 IC4.15
N$282
  Bottom 0.381: SV31.8 IC16.9
N$283
  Bottom 0.381: SV31.7 IC16.10
N$284
  Bottom 0.381: SV31.6 IC16.11
N$285
  Bottom 0.381: SV31.5 IC16.12
N$286
  Bottom 0.381: SV31.4 IC16.13
N$287
  Bottom 0.381: SV31.3 IC16.14
N$288
  Bottom 0.381: SV31.2 IC16.15
N$289
  Bottom 0.381: SV40.2 IC8.15
N$290
  Bottom 0.381: SV40.3 IC8.14
N$291
  Bottom 0.381: SV40.4 IC8.13
N$292
  Bottom 0.381: SV40.5 IC8.12
N$293
  Bottom 0.381: SV40.6 IC8.11
N$294
  Bottom 0.381: SV40.7 IC8.10
N$295
  Bottom 0.381: SV40.8 IC8.9
N$296
  Bottom 0.381: SV29.2 IC22.15
N$297
  Bottom 0.381: SV29.3 IC22.14
N$298
  Bottom 0.381: SV29.4 IC22.13
N$299
  Bottom 0.381: SV29.5 IC22.12
N$300
  Bottom 0.381: SV29.6 IC22.11
N$301
  Bottom 0.381: SV29.7 IC22.10
N$302
  Bottom 0.381: SV29.8 IC22.9
N$303
  Bottom 0.381: SV30.2 IC19.15
N$304
  Bottom 0.381: SV30.3 IC19.14
N$305
  Bottom 0.381: SV30.4 IC19.13
N$306
  Bottom 0.381: SV30.5 IC19.12
N$307
  Bottom 0.381: SV30.6 IC19.11
N$308
  Bottom 0.381: SV30.7 IC19.10
N$309
  Bottom 0.381: SV30.8 IC19.9
N$310
  Bottom 0.381: SV37.2 IC23.15
N$311
  Bottom 0.381: SV37.3 IC23.14
N$312
  Bottom 0.381: SV37.4 IC23.13
N$313
  Bottom 0.381: SV37.5 IC23.12
N$314
  Bottom 0.381: SV37.6 IC23.11
N$315
  Bottom 0.381: SV37.7 IC23.10
N$316
  Bottom 0.381: SV37.8 IC23.9
N$317
  Bottom 0.381: IC12.7 SV41.2
N$318
  Bottom 0.381: IC12.6 SV41.3
N$319
  Bottom 0.381: IC12.5 SV41.4
N$320
  Bottom 0.381: IC12.4 SV41.5
N$321
  Bottom 0.381: IC12.3 SV41.6
N$322
  Bottom 0.381: IC12.2 SV41.7
N$323
  Bottom 0.381: IC12.1 SV41.8
N$324
  Bottom 0.381: IC18.7 SV42.2
N$325
  Bottom 0.381: IC18.6 SV42.3
N$326
  Bottom 0.381: IC18.5 SV42.4
N$327
  Bottom 0.381: IC18.4 SV42.5
N$328
  Bottom 0.381: IC18.3 SV42.6
N$329
  Bottom 0.381: IC18.2 SV42.7
N$330
  Bottom 0.381: IC18.1 SV42.8
N$331
  Bottom 0.381: IC21.7 SV43.2
N$332
  Bottom 0.381: IC21.6 SV43.3
N$333
  Bottom 0.381: IC21.5 SV43.4
N$334
  Bottom 0.381: IC21.4 SV43.5
N$335
  Bottom 0.381: IC21.3 SV43.6
N$336
  Bottom 0.381: IC21.2 SV43.7
N$337
  Bottom 0.381: IC21.1 SV43.8
N$338
  Bottom 0.381: IC24.7 SV44.2
N$339
  Bottom 0.381: IC24.6 SV44.3
N$340
  Bottom 0.381: IC24.5 SV44.4
N$341
  Bottom 0.381: IC24.4 SV44.5
N$342
  Bottom 0.381: IC24.3 SV44.6
N$343
  Bottom 0.381: IC24.2 SV44.7
N$344
  Bottom 0.381: IC24.1 SV44.8
N$345
  Bottom 0.381: SV45.2 IC24.15
N$346
  Bottom 0.381: SV45.3 IC24.14
N$347
  Bottom 0.381: SV45.4 IC24.13
N$348
  Bottom 0.381: SV45.5 IC24.12
N$349
  Bottom 0.381: SV45.6 IC24.11
N$350
  Bottom 0.381: SV45.7 IC24.10
N$351
  Bottom 0.381: SV45.8 IC24.9
N$352
  Bottom 0.381: SV46.2 IC21.15
N$353
  Bottom 0.381: SV46.3 IC21.14
N$354
  Bottom 0.381: SV46.4 IC21.13
N$355
  Bottom 0.381: SV46.5 IC21.12
N$356
  Bottom 0.381: SV46.6 IC21.11
N$357
  Bottom 0.381: SV46.7 IC21.10
N$358
  Bottom 0.381: SV46.8 IC21.9
N$359
  Bottom 0.381: SV47.2 IC18.15
N$360
  Bottom 0.381: SV47.3 IC18.14
N$361
  Bottom 0.381: SV47.4 IC18.13
N$362
  Bottom 0.381: SV47.5 IC18.12
N$363
  Bottom 0.381: SV47.6 IC18.11
N$364
  Bottom 0.381: SV47.7 IC18.10
N$365
  Bottom 0.381: SV47.8 IC18.9
N$366
  Bottom 0.381: SV48.2 IC12.15
N$367
  Bottom 0.381: SV48.3 IC12.14
N$368
  Bottom 0.381: SV48.4 IC12.13
N$369
  Bottom 0.381: SV48.5 IC12.12
N$370
  Bottom 0.381: SV48.6 IC12.11
N$371
  Bottom 0.381: SV48.7 IC12.10
N$372
  Bottom 0.381: SV48.8 IC12.9
P1
  Top 0.381: U$3.13 17.78,41.27 13.97,41.27 U$4.P1
P2
  Bottom 0.381: U$5.13 21.59,42.55 13.97,42.55 U$4.P2
R1
  Top 0.381: U$3.14 17.78,44.45 13.97,44.45 U$4.R1
R2
  Bottom 0.381: U$5.14 21.59,45.72 13.97,45.72 U$4.R2
S1
  Top 0.381: U$3.15 17.78,47.62 13.97,47.62 U$4.S1
S2
  Bottom 0.381: U$5.15 21.59,48.9 13.97,48.9 U$4.S2
T1
  Top 0.381: U$3.16 17.78,50.8 13.97,50.8 U$4.T1
T2
  Bottom 0.381: U$5.16 21.59,52.07 13.97,52.07 U$4.T2
U1
  Top 0.381: U$3.17 17.78,53.98 13.97,53.98 U$4.U1
U2
  Bottom 0.381: U$5.17 21.59,55.24 13.97,55.24 U$4.U2
V1
  Top 0.381: U$3.18 17.78,57.15 13.97,57.15 U$4.V1
V2
  Bottom 0.381: U$5.18 21.59,58.42 13.97,58.42 U$4.V2
VCC
  Top 0.381: 40.64,90.17 44.45,90.17 45.72,91.44 | 45.72,91.44 46.99,92.71 SV40.1 IC8.16 53.34,102.87 53.34,110.49 | 40.64,90.17 C15.1 | 45.72,91.44 50.17,91.44 51.44,90.17 C17.1 | 40.64,90.17 40.64,82.55 IC12.16 SV48.1 46.99,61.59 45.72,60.33 45.72,50.8 46.99,49.53 IC3.16 SV24.1 46.99,43.18 | SV31.1 69.85,111.76 73.03,111.76 74.3,110.49 C19.1 83.19,110.49 84.46,109.22 89.54,109.22 | SV31.1 IC16.16 | IC4.16 SV32.1 46.99,111.76 | 45.09,111.76 41.28,111.76 40.01,110.49 C13.1 | 45.09,111.76 46.36,110.49 C14.1 | 53.34,110.49 51.44,110.49 50.17,111.76 46.99,111.76 | 46.99,111.76 45.09,111.76 | 53.34,110.49 C16.1 64.77,110.49 67.31,113.03 SV31.1 | SV47.1 IC18.16 73.66,82.55 73.66,90.81 | 67.31,91.44 C18.1 | 67.31,91.44 SV39.1 IC17.16 | 73.66,90.81 73.03,91.44 67.31,91.44 | 73.66,90.81 74.3,90.17 C21.1 87.63,90.17 90.17,92.71 | IC23.16 SV37.1 110.49,113.03 107.95,110.49 C22.1 94.62,110.49 93.35,111.76 90.17,111.76 | 90.17,111.76 C20.1 90.17,109.86 89.54,109.22 | 90.17,111.76 SV45.1 IC24.16 | IC22.16 SV29.1 C24.1 110.49,89.53 109.22,88.27 109.22,77.47 | SV46.1 IC21.16 109.22,77.47 | SV30.1 IC19.16 95.89,81.92 | 96.52,90.17 94.62,90.17 93.35,91.44 91.44,91.44 90.17,92.71 | 96.52,90.17 C23.1 | 95.89,81.92 96.52,82.55 96.52,90.17 | 109.22,77.47 104.78,81.92 95.89,81.92 | 89.54,109.22 88.9,108.58 88.9,99.06 90.17,97.79 IC20.16 SV38.1 90.17,92.71 | SV8.1 IC1.16 40.64,13.97 40.64,21.59 | 40.64,21.59 44.45,21.59 45.72,22.86 | 45.72,22.86 46.99,24.13 SV16.1 IC2.16 53.34,34.29 53.34,41.91 | 40.64,21.59 C1.1 34.29,20.95 33.02,19.68 33.02,13.97 27.94,8.89 27.94,8.26 24.13,4.45 U$5.1 | 45.72,22.86 50.17,22.86 51.44,21.59 C2.1
  Top 0.381: SV23.1 69.85,43.18 73.03,43.18 74.3,41.91 C11.1 83.19,41.91 84.46,40.64 89.54,40.64 | SV23.1 IC7.16 | 45.09,43.18 41.28,43.18 40.01,41.91 C9.1 | 45.09,43.18 46.36,41.91 C5.1 | 53.34,41.91 51.44,41.91 50.17,43.18 46.99,43.18 | 46.99,43.18 45.09,43.18 | 53.34,41.91 C10.1 64.77,41.91 67.31,44.45 SV23.1 | SV7.1 IC5.16 73.66,13.97 73.66,22.23 | 67.31,22.86 C6.1 | 67.31,22.86 SV15.1 IC6.16 | 73.66,22.23 73.03,22.86 67.31,22.86 | 73.66,22.23 74.3,21.59 C3.1 87.63,21.59 90.17,24.13 | IC15.16 SV21.1 110.49,44.45 107.95,41.91 C12.1 94.62,41.91 93.35,43.18 90.17,43.18 | 90.17,43.18 C7.1 90.17,41.27 89.54,40.64 | 90.17,43.18 SV22.1 IC11.16 | IC14.16 SV13.1 C8.1 110.49,20.95 109.22,19.68 109.22,8.89 | SV5.1 IC13.16 109.22,8.89 | SV6.1 IC9.16 95.89,13.34 | 96.52,21.59 94.62,21.59 93.35,22.86 91.44,22.86 90.17,24.13 | 96.52,21.59 C4.1 | 95.89,13.34 96.52,13.97 96.52,21.59 | 109.22,8.89 104.78,13.34 95.89,13.34 | 89.54,40.64 88.9,40.01 88.9,30.48 90.17,29.21 IC10.16 SV14.1 90.17,24.13
  Bottom 0.381: U$4.A2 13.97,4.45 21.59,4.45 U$5.1

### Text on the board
Top: VRS | 8i/8L Prototype
Bottom: VRS | 8i/8L Prototype
tPlace: 8i/8L Prototype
